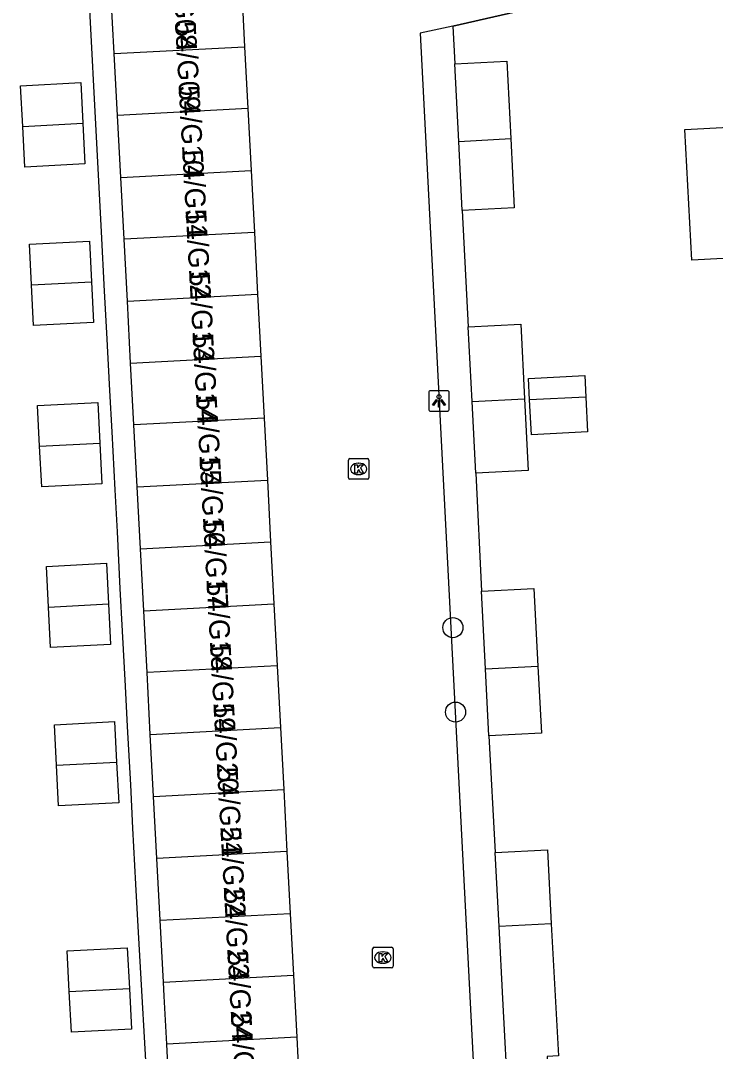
# Model space of a CAD drawing. Extents: x 158087 to 159494, y 382905 to 383981.
# Drawn here: x 158916.3 to 158950.2, y 383503.3 to 383553.5 of the extents above; entities that cross this region are included whole.
import ezdxf

# ---------------------------------------------------------------- set-up
doc = ezdxf.new("R2010")
doc.units = 0
for name, color, linetype in [('IMGEO_Boom', 7, 'Continuous'), ('IMGEO_Kolk', 7, 'Continuous'), ('IMGEO_Lichtpunt', 7, 'Continuous'), ('IMGEO_Muur', 7, 'Continuous'), ('IMGEO_Pand', 7, 'Continuous'), ('IMGEO_Pand_nummerreeks', 7, 'Continuous'), ('IMGEO_Pand_vergunning_verleend', 7, 'Continuous'), ('IMGEO_Rijbaan_lokaal_open', 7, 'Continuous'), ('IMGEO_Voetpad_open', 7, 'Continuous')]:
    doc.layers.add(name, color=color, linetype=linetype)

msp = doc.modelspace()

# ---------------------------------------------------------------- linework, layer by layer
at = {"layer": 'IMGEO_Boom'}
for centre in [(158937.365, 383523.938), (158937.493, 383519.825)]:
    msp.add_circle(centre, 0.489, dxfattribs=at)
at = {"layer": 'IMGEO_Kolk'}
for p, q in [((158932.273, 383531.243), (158932.273, 383532.095)), ((158932.348, 383532.169), (158933.2, 383532.169)), ((158933.274, 383532.095), (158933.274, 383531.243)), ((158932.761, 383531.949), (158932.786, 383531.949)), ((158933.2, 383531.169), (158932.348, 383531.169)), ((158932.784, 383531.389), (158932.759, 383531.389)), ((158933.452, 383507.441), (158933.452, 383508.293)), ((158933.527, 383508.367), (158934.379, 383508.367)), ((158933.94, 383508.147), (158933.965, 383508.147)), ((158934.453, 383508.293), (158934.453, 383507.441)), ((158934.379, 383507.367), (158933.527, 383507.367)), ((158933.963, 383507.587), (158933.938, 383507.587))]:
    msp.add_line(p, q, dxfattribs=at)
for points in [[(158932.273, 383531.243), (158932.273, 383532.095)], [(158932.348, 383532.169), (158933.2, 383532.169)], [(158933.274, 383532.095), (158933.274, 383531.243)], [(158932.594, 383531.869), (158932.717, 383531.869), (158932.717, 383531.718), (158932.847, 383531.869), (158933.011, 383531.869), (158932.865, 383531.718), (158933.018, 383531.469), (158932.866, 383531.469), (158932.781, 383531.633), (158932.717, 383531.566), (158932.717, 383531.469), (158932.594, 383531.469), (158932.594, 383531.869)], [(158933.2, 383531.169), (158932.348, 383531.169)], [(158933.452, 383507.441), (158933.452, 383508.293)], [(158933.527, 383508.367), (158934.379, 383508.367)], [(158933.773, 383508.067), (158933.896, 383508.067), (158933.896, 383507.916), (158934.026, 383508.067), (158934.19, 383508.067), (158934.044, 383507.916), (158934.197, 383507.667), (158934.045, 383507.667), (158933.96, 383507.831), (158933.896, 383507.764), (158933.896, 383507.667), (158933.773, 383507.667), (158933.773, 383508.067)], [(158934.453, 383508.293), (158934.453, 383507.441)], [(158934.379, 383507.367), (158933.527, 383507.367)]]:
    msp.add_lwpolyline(points, dxfattribs=at)
for centre, start, end in [((158932.35, 383532.093), 91.552, 178.448), ((158932.35, 383532.093), 91.552, 178.448), ((158933.198, 383532.093), 1.552, 88.448), ((158933.198, 383532.093), 1.552, 88.448), ((158932.35, 383531.245), 181.552, 268.448), ((158932.35, 383531.245), 181.552, 268.448), ((158933.198, 383531.245), 271.552, 358.448), ((158933.198, 383531.245), 271.552, 358.448), ((158933.529, 383508.291), 91.552, 178.448), ((158933.529, 383508.291), 91.552, 178.448), ((158934.377, 383508.291), 1.552, 88.448), ((158934.377, 383508.291), 1.552, 88.448), ((158933.529, 383507.443), 181.552, 268.448), ((158933.529, 383507.443), 181.552, 268.448), ((158934.377, 383507.443), 271.552, 358.448), ((158934.377, 383507.443), 271.552, 358.448)]:
    msp.add_arc(centre, 0.0765, start, end, dxfattribs=at)
for centre, major_axis, ratio, start_param, end_param in [((158932.76, 383531.669), (-0.387, 0.002), 0.722429, 4.712389, 7.853982), ((158932.785, 383531.669), (-0.39, 0.002), 0.717154, 1.570796, 4.712389), ((158933.939, 383507.867), (-0.387, 0.002), 0.722429, 4.712389, 7.853982), ((158933.964, 383507.867), (-0.39, 0.002), 0.717154, 1.570796, 4.712389)]:
    msp.add_ellipse(centre, major_axis=major_axis, ratio=ratio, start_param=start_param, end_param=end_param, dxfattribs=at)
at = {"layer": 'IMGEO_Lichtpunt'}
for p, q in [((158936.188, 383535.384), (158936.188, 383534.577)), ((158936.188, 383535.384), (158936.188, 383534.577)), ((158937.09, 383535.479), (158936.282, 383535.479)), ((158937.09, 383535.479), (158936.282, 383535.479)), ((158937.184, 383534.577), (158937.184, 383535.384)), ((158937.184, 383534.577), (158937.184, 383535.384)), ((158936.282, 383534.483), (158937.09, 383534.483)), ((158936.282, 383534.483), (158937.09, 383534.483))]:
    msp.add_line(p, q, dxfattribs=at)
for points in [[(158936.562, 383535.048), (158936.601, 383535.02), (158936.413, 383534.758), (158936.375, 383534.785), (158936.562, 383535.048)], [(158936.664, 383535), (158936.711, 383535), (158936.711, 383534.678), (158936.664, 383534.678), (158936.664, 383535)], [(158936.774, 383535.02), (158936.812, 383535.047), (158936.999, 383534.785), (158936.96, 383534.757), (158936.774, 383535.02)]]:
    msp.add_lwpolyline(points, dxfattribs=at)
msp.add_circle((158936.687, 383535.182), 0.0994, dxfattribs=at)
for centre, start, end in [((158936.282, 383535.384), 90, 180), ((158936.282, 383535.384), 90, 180), ((158937.09, 383535.384), 0, 90), ((158937.09, 383535.384), 0, 90), ((158936.282, 383534.577), 180, 270), ((158936.282, 383534.577), 180, 270), ((158937.09, 383534.577), 270, 0), ((158937.09, 383534.577), 270, 360)]:
    msp.add_arc(centre, 0.0946, start, end, dxfattribs=at)
at = {"layer": 'IMGEO_Muur'}
msp.add_lwpolyline([(158937.365, 383553.243), (158941.721, 383554.23)], dxfattribs=at)
at = {"layer": 'IMGEO_Pand'}
for points in [[(158927.062, 383555.252), (158927.22, 383552.237)], [(158920.868, 383551.9), (158920.708, 383554.916)], [(158920.868, 383551.9), (158927.22, 383552.237)], [(158927.22, 383552.237), (158927.379, 383549.221)], [(158921.028, 383548.885), (158920.868, 383551.9)], [(158937.459, 383551.398), (158939.992, 383551.527), (158940.185, 383547.757)], [(158937.652, 383547.623), (158937.459, 383551.398)], [(158927.379, 383549.221), (158921.028, 383548.885)], [(158927.379, 383549.221), (158927.537, 383546.206)], [(158921.188, 383545.869), (158921.028, 383548.885)], [(158953.281, 383542.068), (158949.007, 383541.841), (158948.669, 383548.208), (158952.951, 383548.435)], [(158937.652, 383547.623), (158940.185, 383547.757)], [(158937.824, 383544.262), (158937.652, 383547.623)], [(158940.185, 383547.757), (158940.357, 383544.392), (158937.824, 383544.262)], [(158921.188, 383545.869), (158927.537, 383546.206)], [(158927.537, 383546.206), (158927.696, 383543.19)], [(158921.347, 383542.854), (158921.188, 383545.869)], [(158927.696, 383543.19), (158921.347, 383542.854)], [(158927.696, 383543.19), (158927.854, 383540.174)], [(158921.507, 383539.838), (158921.347, 383542.854)], [(158921.507, 383539.838), (158927.854, 383540.174)], [(158927.854, 383540.174), (158928.013, 383537.159)], [(158921.667, 383536.823), (158921.507, 383539.838)], [(158938.116, 383538.583), (158940.667, 383538.713), (158940.853, 383535.086)], [(158938.302, 383534.95), (158938.116, 383538.583)], [(158921.667, 383536.823), (158928.013, 383537.159)], [(158928.013, 383537.159), (158928.171, 383534.143)], [(158921.827, 383533.809), (158921.667, 383536.823)], [(158941.1, 383535.03), (158941.046, 383536.078), (158943.787, 383536.218), (158943.841, 383535.17)], [(158938.302, 383534.95), (158940.853, 383535.086)], [(158940.853, 383535.086), (158941.031, 383531.598), (158938.48, 383531.469)], [(158943.841, 383535.17), (158943.927, 383533.472), (158941.187, 383533.332), (158941.1, 383535.03)], [(158943.841, 383535.17), (158941.1, 383535.03)], [(158938.48, 383531.469), (158938.302, 383534.95)], [(158928.171, 383534.143), (158921.827, 383533.809)], [(158928.171, 383534.143), (158928.33, 383531.128)], [(158921.987, 383530.792), (158921.827, 383533.809)], [(158921.987, 383530.792), (158928.33, 383531.128)], [(158928.33, 383531.128), (158928.488, 383528.112)], [(158922.146, 383527.776), (158921.987, 383530.792)], [(158922.146, 383527.776), (158928.488, 383528.112)], [(158928.488, 383528.112), (158928.647, 383525.097)], [(158922.306, 383524.761), (158922.146, 383527.776)], [(158938.761, 383525.719), (158941.312, 383525.849), (158941.506, 383522.067)], [(158938.955, 383521.931), (158938.761, 383525.719)], [(158922.306, 383524.761), (158928.647, 383525.097)], [(158928.647, 383525.097), (158928.805, 383522.081)], [(158922.466, 383521.745), (158922.306, 383524.761)], [(158928.805, 383522.081), (158922.466, 383521.745)], [(158928.805, 383522.081), (158928.964, 383519.066)], [(158938.955, 383521.931), (158941.506, 383522.067)], [(158939.122, 383518.666), (158938.955, 383521.931)], [(158941.506, 383522.067), (158941.673, 383518.797), (158939.122, 383518.666)], [(158922.626, 383518.73), (158922.466, 383521.745)], [(158922.626, 383518.73), (158928.964, 383519.066)], [(158928.964, 383519.066), (158929.122, 383516.05)], [(158922.785, 383515.714), (158922.626, 383518.73)], [(158922.785, 383515.714), (158929.122, 383516.05)], [(158929.122, 383516.05), (158929.281, 383513.034)], [(158922.945, 383512.699), (158922.785, 383515.714)], [(158929.281, 383513.034), (158922.945, 383512.699)], [(158929.281, 383513.034), (158929.439, 383510.019)], [(158939.428, 383512.981), (158941.966, 383513.111), (158942.15, 383509.514)], [(158939.612, 383509.379), (158939.428, 383512.981)], [(158923.105, 383509.683), (158922.945, 383512.699)], [(158923.105, 383509.683), (158929.439, 383510.019)], [(158929.439, 383510.019), (158929.598, 383507.003)], [(158923.265, 383506.668), (158923.105, 383509.683)], [(158942.15, 383509.514), (158939.612, 383509.379)], [(158940.066, 383500.685), (158939.792, 383505.866), (158939.612, 383509.379)], [(158942.15, 383509.514), (158942.504, 383503.083), (158941.956, 383503.051), (158942.077, 383500.804), (158940.066, 383500.685)], [(158923.265, 383506.668), (158929.598, 383507.003)], [(158929.598, 383507.003), (158929.756, 383503.988)], [(158923.424, 383503.652), (158923.301, 383505.99), (158923.265, 383506.668)], [(158929.756, 383503.988), (158923.424, 383503.652)], [(158929.756, 383503.988), (158929.915, 383500.972)], [(158923.584, 383500.637), (158923.424, 383503.652)]]:
    msp.add_lwpolyline(points, dxfattribs=at)
at = {"layer": 'IMGEO_Pand_vergunning_verleend'}
for points in [[(158916.409, 383548.355), (158916.308, 383550.335), (158919.236, 383550.484), (158919.337, 383548.504)], [(158916.409, 383548.355), (158919.337, 383548.504)], [(158919.337, 383548.504), (158919.437, 383546.524), (158916.51, 383546.375), (158916.409, 383548.355)], [(158916.833, 383540.63), (158916.733, 383542.609), (158919.66, 383542.758), (158919.761, 383540.779)], [(158916.833, 383540.63), (158919.761, 383540.779)], [(158919.761, 383540.779), (158919.862, 383538.799), (158916.934, 383538.65), (158916.833, 383540.63)], [(158917.236, 383532.78), (158917.135, 383534.759), (158920.062, 383534.908), (158920.163, 383532.929)], [(158917.236, 383532.78), (158920.163, 383532.929)], [(158920.163, 383532.929), (158920.264, 383530.949), (158917.336, 383530.8), (158917.236, 383532.78)], [(158917.663, 383524.943), (158917.562, 383526.923), (158920.49, 383527.072), (158920.59, 383525.092)], [(158917.663, 383524.943), (158920.59, 383525.092)], [(158920.59, 383525.092), (158920.691, 383523.112), (158917.764, 383522.963), (158917.663, 383524.943)], [(158918.057, 383517.231), (158917.956, 383519.211), (158920.884, 383519.36), (158920.984, 383517.38)], [(158918.057, 383517.231), (158920.984, 383517.38)], [(158920.984, 383517.38), (158921.085, 383515.4), (158918.158, 383515.252), (158918.057, 383517.231)], [(158918.678, 383506.211), (158918.577, 383508.19), (158921.505, 383508.339), (158921.606, 383506.359)], [(158918.678, 383506.211), (158921.606, 383506.359)], [(158921.606, 383506.359), (158921.706, 383504.38), (158918.779, 383504.231), (158918.678, 383506.211)]]:
    msp.add_lwpolyline(points, dxfattribs=at)
at = {"layer": 'IMGEO_Rijbaan_lokaal_open'}
for points in [[(158964.491, 383559.355), (158941.721, 383554.23), (158937.365, 383553.243)], [(158937.365, 383553.243), (158935.766, 383552.9), (158938.491, 383500), (158941.975, 383432.354)]]:
    msp.add_lwpolyline(points, dxfattribs=at)
at = {"layer": 'IMGEO_Voetpad_open'}
for points in [[(158922.537, 383500.587), (158922.033, 383509.385), (158921.925, 383511.435), (158921.781, 383514.164), (158921.669, 383516.284), (158921.52, 383519.118), (158921.416, 383521.084), (158921.275, 383523.758), (158921.165, 383525.852), (158921.02, 383528.602), (158920.911, 383530.656), (158920.762, 383533.482), (158920.657, 383535.483), (158920.508, 383538.305), (158920.402, 383540.32), (158920.25, 383543.21), (158919.424, 383558.978)], [(158937.365, 383553.243), (158937.459, 383551.398)], [(158937.824, 383544.262), (158938.116, 383538.583)], [(158938.48, 383531.469), (158938.761, 383525.719)], [(158939.122, 383518.666), (158939.428, 383512.981)]]:
    msp.add_lwpolyline(points, dxfattribs=at)

# ---------------------------------------------------------------- texts
at = {"layer": 'IMGEO_Pand_nummerreeks'}
for s, p in [('54/G08', (158923.659, 383556.451)), ('54/G09', (158923.829, 383553.44)), ('54/G10', (158924.004, 383550.325)), ('54/G11', (158924.18, 383547.201)), ('54/G12', (158924.343, 383544.3)), ('54/G13', (158924.514, 383541.277)), ('54/G14', (158924.683, 383538.259)), ('54/G15', (158924.853, 383535.242)), ('54/G16', (158925.023, 383532.225)), ('54/G17', (158925.193, 383529.207)), ('54/G18', (158925.363, 383526.187)), ('54/G19', (158925.533, 383523.176)), ('54/G20', (158925.698, 383520.243)), ('54/G21', (158925.874, 383517.119)), ('54/G22', (158926.037, 383514.218)), ('54/G23', (158926.207, 383511.194)), ('54/G24', (158926.377, 383508.177)), ('54/G25', (158926.547, 383505.16))]:
    msp.add_text(s, height=1, rotation=273.2226, dxfattribs=at).set_placement(p)

doc.saveas('drawing.dxf')
